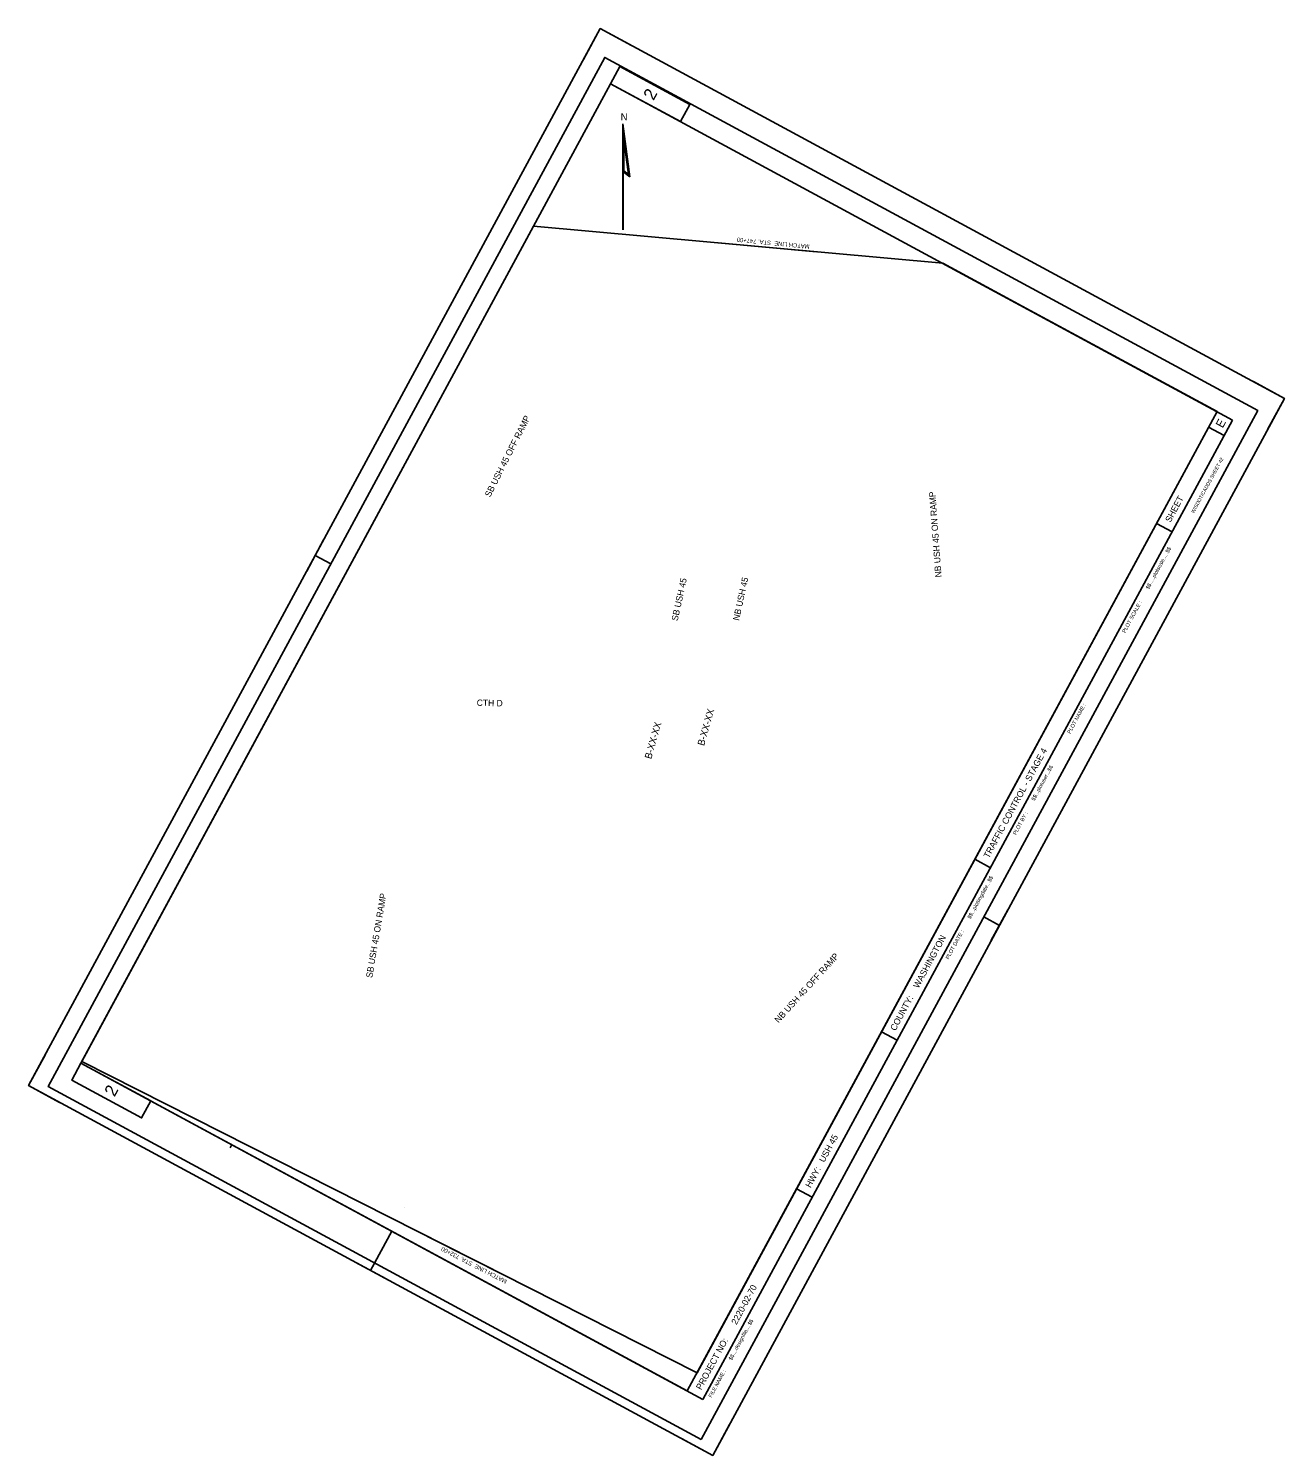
# Model space of a CAD drawing. Extents: x 355543 to 357319, y 194915 to 196934.
import ezdxf

# ---------------------------------------------------------------- set-up
doc = ezdxf.new("R2010")
doc.units = 0
for name, color, linetype in [('Default', 7, 'Continuous'), ('P_ALI_100_Equation', 7, 'Continuous'), ('P_ALI_100_PIData', 7, 'Continuous'), ('P_ALI_20', 7, 'Continuous'), ('P_ALI_200_Equation', 7, 'Continuous'), ('P_ALI_20_Sta', 7, 'Continuous'), ('P_ALI_20_Tic', 7, 'Continuous'), ('P_ALI_50_Equation', 7, 'Continuous'), ('P_ALI_50_Tic', 7, 'Continuous')]:
    doc.layers.add(name, color=color, linetype=linetype)

msp = doc.modelspace()

# ---------------------------------------------------------------- linework, layer by layer
for p, q in [((356327.9, 196889.6), (356351.7, 196933.5)), ((356395.7, 196909.7), (356351.7, 196933.5)), ((355617.1, 195470.1), (356366.3, 196855.4)), ((357245.9, 196379.7), (356366.3, 196855.4)), ((357319.3, 196410.2), (357275.3, 196434)), ((356474.7, 195006.2), (357223.9, 196391.6)), ((357295.5, 196366.3), (357319.3, 196410.2)), ((356496.7, 194994.3), (357245.9, 196379.7)), ((357234, 196357.7), (357212, 196369.6)), ((357160.3, 196221.4), (357138.3, 196233.3)), ((355936.7, 196166.1), (355960.4, 196210.1)), ((355948.6, 196188.1), (355970.5, 196176.2)), ((356903.4, 195746.4), (356881.4, 195758.3)), ((356904.2, 195642.8), (356928, 195686.8)), ((356916.1, 195664.8), (356894.1, 195676.7)), ((356771.4, 195502.3), (356749.4, 195514.2)), ((355543, 195438.2), (355566.8, 195482.2)), ((356496.7, 194994.3), (355617.1, 195470.1)), ((355587, 195414.4), (355543, 195438.2)), ((355830.4, 195354.7), (355828, 195350.3)), ((356651.3, 195280.2), (356629.3, 195292.1)), ((356074.7, 195265.2), (356074.7, 195265.2)), ((356026.8, 195176.6), (356056.9, 195232.2)), ((356048.8, 195164.7), (356004.8, 195188.5)), ((356510.6, 194914.9), (356534.3, 194958.9)), ((356510.6, 194914.9), (356466.6, 194938.7))]:
    msp.add_line(p, q)
for points in [[(356366.3, 196855.4), (356379.4, 196879.6), (356478.4, 196826.1), (356465.3, 196801.9)], [(355617.1, 195470.1), (355604, 195445.9), (355702.9, 195392.4), (355716, 195416.6)]]:
    msp.add_lwpolyline(points, close=True)
at = {"layer": 'Default'}
msp.add_lwpolyline([(355618.3, 195472.4), (356488.5, 195031.7), (357223.9, 196391.6), (356959.4, 196534.7), (356835.9, 196601.5), (356257.4, 196654)], close=True, dxfattribs=at)
msp.add_lwpolyline([(355618.3, 195472.4), (356488.5, 195031.7), (357223.9, 196391.6), (356959.4, 196534.7), (356835.9, 196601.5), (356257.4, 196654)], close=True, dxfattribs=at)
msp.add_lwpolyline([(355618.3, 195472.4), (356488.5, 195031.7), (357223.9, 196391.6), (356959.4, 196534.7), (356835.9, 196601.5), (356257.4, 196654)], close=True, dxfattribs=at)
at = {"layer": 'P_ALI_100_Equation'}
for p, q in [((356393.6, 196723.7), (356383.6, 196798.7)), ((356383.6, 196731.2), (356383.6, 196798.7)), ((356384.4, 196731.6), (356384.4, 196787.4)), ((356392.6, 196725.4), (356384.4, 196787.4)), ((356385.1, 196732), (356385.1, 196776.1)), ((356391.7, 196727.1), (356385.1, 196776.1)), ((356383.6, 196731.2), (356393.6, 196723.7)), ((356383.6, 196648.7), (356383.6, 196731.2)), ((356383.9, 196648.7), (356383.9, 196731)), ((356384.4, 196731.6), (356392.6, 196725.4)), ((356385.1, 196732), (356391.7, 196727.1))]:
    msp.add_line(p, q, dxfattribs=at)
msp.add_lwpolyline([(356383.6, 196798.7), (356383.6, 196798.7)], dxfattribs=at)
at = {"layer": 'P_ALI_20'}
for points in [[(356510.6, 194914.9), (357319.3, 196410.2), (356351.7, 196933.5), (355543, 195438.2)], [(356494.3, 194937.4), (357281.6, 196393.1), (356358, 196892.6), (355570.7, 195436.9)]]:
    msp.add_lwpolyline(points, close=True, dxfattribs=at)
at = {"layer": 'P_ALI_200_Equation'}
msp.add_lwpolyline([(355543, 195438.2), (356351.7, 196933.5), (357319.3, 196410.2), (356510.6, 194914.9), (355543, 195438.2)], dxfattribs=at)
at = {"layer": 'P_ALI_20_Sta'}
msp.add_lwpolyline([(355543, 195438.2), (356351.7, 196933.5), (357319.3, 196410.2), (356510.6, 194914.9)], close=True, dxfattribs=at)
at = {"layer": 'P_ALI_20_Tic'}
for p, q in [((356518.5, 196630.3), (356657.3, 196617.7)), ((356107.4, 195224.7), (356231.6, 195161.8))]:
    msp.add_line(p, q, dxfattribs=at)
at = {"layer": 'P_ALI_50_Tic'}
for points in [[(356366.3, 196855.4), (355617.1, 195470.1)], [(355617.1, 195470.1), (356474.7, 195006.2), (357223.9, 196391.6)]]:
    msp.add_lwpolyline(points, dxfattribs=at)

# ---------------------------------------------------------------- texts
for s, height, p in [('2', 17.5, (356426.9, 196830.8)), ('E', 12, (357231.9, 196367.5)), ('WISDOT/CADDS SHEET 42', 5, (357191.4, 196247.4)), ('SHEET ', 9, (357158, 196234)), ('$$.....plotscale.....$$', 5.4, (357127.5, 196139.7)), ('PLOT SCALE : ', 5.4, (357094.1, 196077.9)), ('PLOT NAME :                      ', 5.4, (357016.4, 195935.4)), ('TRAFFIC CONTROL - STAGE 4', 9, (356901.1, 195759)), ('$$...plotuser...$$', 5.4, (356965.7, 195840.6)), ('PLOT BY :', 5.4, (356939.6, 195792.2)), ('$$...plottingdate...$$', 5.4, (356875.3, 195673.5)), (' WASHINGTON', 9, (356800, 195572.1)), ('PLOT DATE :', 5.4, (356844.4, 195616.3)), ('COUNTY:', 9, (356769.1, 195514.9)), ('2', 17.5, (355664.6, 195421.3)), (' USH 45', 9, (356666.8, 195325.8)), ('HWY:', 9, (356649, 195292.8)), (' 2220-02-70', 9, (356542.7, 195096.2)), ('$$....designfile....$$', 5.4, (356537.6, 195049)), ('PROJECT NO:', 9, (356494.4, 195006.9)), ('FILE NAME :', 5.4, (356509, 194996.2))]:
    msp.add_text(s, height=height, rotation=61.5935).set_placement(p)
at = {"layer": 'P_ALI_100_Equation'}
msp.add_text('N', height=10, dxfattribs=at).set_placement((356380.5, 196803.7))
at = {"layer": 'P_ALI_100_PIData'}
for p in [(356498.4, 195918.1), (356423.7, 195899.4)]:
    msp.add_text('B-XX-XX', height=10, rotation=74.2018, dxfattribs=at).set_placement(p)
at = {"layer": 'P_ALI_50_Equation'}
for s, height, rotation, p in [('MATCH LINE  STA. 747+00', 6, 174.3993, (356647.9, 196627.8)), ('SB USH 45 OFF RAMP', 9, 63.2445, (356195.8, 196269.8)), ('NB USH 45 ON RAMP', 9, 94.24, (356834.5, 196157.5)), ('SB USH 45', 9, 77.678, (356461, 196094.9)), ('NB USH 45', 9, 77.678, (356547.9, 196095.4)), ('CTH D', 9, 358.6925, (356176.8, 195975.4)), ('SB USH 45 ON RAMP', 9, 80.3909, (356029.1, 195590.1)), ('NB USH 45 OFF RAMP', 9, 47.6792, (356603.8, 195526.1)), ('MATCH LINE  STA. 732+00', 6, 152.7261, (356220.4, 195162.9))]:
    msp.add_text(s, height=height, rotation=rotation, dxfattribs=at).set_placement(p)

doc.saveas('drawing.dxf')
